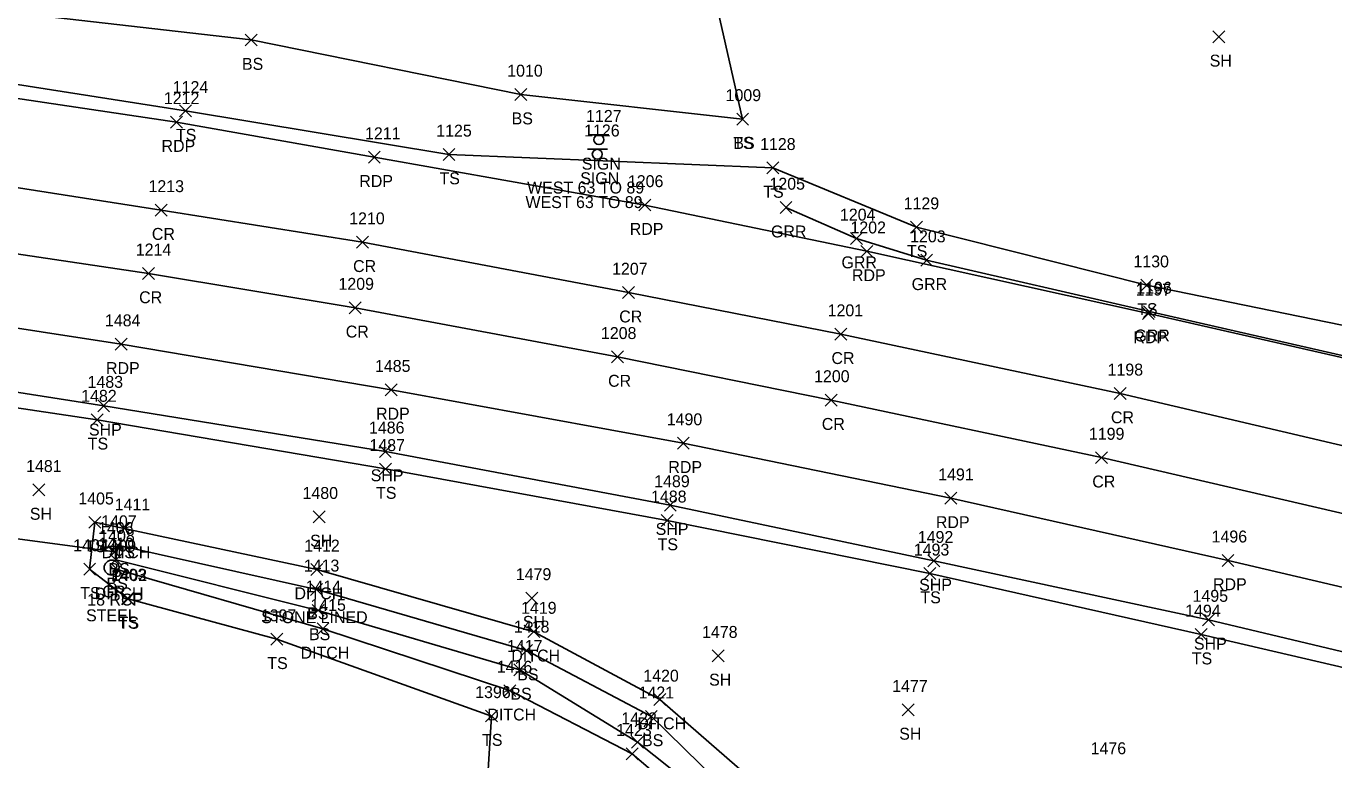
# Model space of a CAD drawing. Extents: x 1629176 to 1637209, y 606063 to 610167.
# Drawn here: x 1629563.1 to 1629782.2, y 606950 to 607073 of the extents above; entities that cross this region are included whole.
import ezdxf

# ---------------------------------------------------------------- set-up
doc = ezdxf.new("R2010")
doc.units = 0
for name, color, linetype in [('D_A', 7, 'Continuous'), ('D_C', 7, 'Continuous'), ('D_I', 7, 'Continuous'), ('D_TIC', 7, 'Continuous'), ('DCP', 7, 'Continuous'), ('DD', 7, 'Continuous'), ('L_A', 7, 'Continuous'), ('L_I', 7, 'Continuous'), ('L_TIC', 7, 'Continuous'), ('LELB', 7, 'Continuous'), ('P_A', 7, 'Continuous'), ('P_I', 7, 'Continuous'), ('P_TIC', 7, 'Continuous'), ('PET', 7, 'Continuous'), ('PRC', 7, 'Continuous'), ('PSP', 7, 'Continuous'), ('R_A', 7, 'Continuous'), ('R_C', 7, 'Continuous'), ('R_I', 7, 'Continuous'), ('R_TIC', 7, 'Continuous'), ('RGP', 7, 'Continuous'), ('RGR', 7, 'Continuous'), ('S_A', 7, 'Continuous'), ('S_C', 7, 'Continuous'), ('S_I', 7, 'Continuous'), ('SSGN', 7, 'Continuous')]:
    doc.layers.add(name, color=color, linetype=linetype)

msp = doc.modelspace()

# ---------------------------------------------------------------- linework, layer by layer
at = {"layer": 'D_TIC'}
for points in [[(1629578.49, 606987.83), (1629580.49, 606989.83)], [(1629580.49, 606987.83), (1629578.49, 606989.83)], [(1629576.96, 606983.89), (1629578.96, 606985.89)], [(1629578.96, 606983.89), (1629576.96, 606985.89)], [(1629577.34, 606980.92), (1629579.34, 606982.92)], [(1629579.34, 606980.92), (1629577.34, 606982.92)], [(1629610.81, 606980.94), (1629612.81, 606982.94)], [(1629612.81, 606980.94), (1629610.81, 606982.94)], [(1629611.83, 606971), (1629613.83, 606973)], [(1629613.83, 606971), (1629611.83, 606973)], [(1629647.15, 606970.51), (1629649.15, 606972.51)], [(1629649.15, 606970.51), (1629647.15, 606972.51)], [(1629643.13, 606960.63), (1629645.13, 606962.63)], [(1629645.13, 606960.63), (1629643.13, 606962.63)], [(1629668.27, 606959.14), (1629670.27, 606961.14)], [(1629670.27, 606959.14), (1629668.27, 606961.14)], [(1629663.65, 606950.05), (1629665.65, 606952.05)], [(1629665.65, 606950.05), (1629663.65, 606952.05)]]:
    msp.add_lwpolyline(points, dxfattribs=at)
at = {"layer": 'DCP'}
msp.add_lwpolyline([(1629240.18, 607029.98), (1629577.96, 606984.89)], dxfattribs=at)
at = {"layer": 'DD'}
for points in [[(1629579.49, 606988.83), (1629611.81, 606981.94), (1629648.15, 606971.51), (1629669.27, 606960.14), (1629688.69, 606943.21), (1629706.7, 606917.47), (1629717.05, 606898.33), (1629732.21, 606867.29)], [(1629578.34, 606981.92), (1629612.83, 606972), (1629644.13, 606961.63), (1629664.65, 606951.05), (1629679.43, 606938.38), (1629699.06, 606909.9), (1629708.92, 606897.3), (1629729.58, 606859.74)]]:
    msp.add_lwpolyline(points, dxfattribs=at)
at = {"layer": 'L_TIC'}
for points in [[(1629599.81, 607069.68), (1629601.81, 607071.68)], [(1629601.81, 607069.68), (1629599.81, 607071.68)], [(1629761.92, 607070.22), (1629763.92, 607072.22)], [(1629763.92, 607070.22), (1629761.92, 607072.22)], [(1629645, 607060.54), (1629647, 607062.54)], [(1629647, 607060.54), (1629645, 607062.54)], [(1629588.78, 607057.79), (1629590.78, 607059.79)], [(1629590.78, 607057.79), (1629588.78, 607059.79)], [(1629682.15, 607056.43), (1629684.15, 607058.43)], [(1629684.15, 607056.43), (1629682.15, 607058.43)], [(1629682.15, 607056.43), (1629684.15, 607058.43)], [(1629684.15, 607056.43), (1629682.15, 607058.43)], [(1629632.94, 607050.49), (1629634.94, 607052.49)], [(1629634.94, 607050.49), (1629632.94, 607052.49)], [(1629687.19, 607048.24), (1629689.19, 607050.24)], [(1629689.19, 607048.24), (1629687.19, 607050.24)], [(1629711.27, 607038.3), (1629713.27, 607040.3)], [(1629713.27, 607038.3), (1629711.27, 607040.3)], [(1629749.85, 607028.57), (1629751.85, 607030.57)], [(1629751.85, 607028.57), (1629749.85, 607030.57)], [(1629574, 607006.04), (1629576, 607008.04)], [(1629576, 607006.04), (1629574, 607008.04)], [(1629622.31, 606997.78), (1629624.31, 606999.78)], [(1629624.31, 606997.78), (1629622.31, 606999.78)], [(1629564.21, 606994.27), (1629566.21, 606996.27)], [(1629566.21, 606994.27), (1629564.21, 606996.27)], [(1629573.6, 606988.84), (1629575.6, 606990.84)], [(1629575.6, 606988.84), (1629573.6, 606990.84)], [(1629611.18, 606989.76), (1629613.18, 606991.76)], [(1629613.18, 606989.76), (1629611.18, 606991.76)], [(1629669.49, 606989.16), (1629671.49, 606991.16)], [(1629671.49, 606989.16), (1629669.49, 606991.16)], [(1629578.49, 606987.83), (1629580.49, 606989.83)], [(1629580.49, 606987.83), (1629578.49, 606989.83)], [(1629577.44, 606985.01), (1629579.44, 606987.01)], [(1629579.44, 606985.01), (1629577.44, 606987.01)], [(1629577.44, 606985.01), (1629579.44, 606987.01)], [(1629579.44, 606985.01), (1629577.44, 606987.01)], [(1629577.11, 606982.58), (1629579.11, 606984.58)], [(1629579.11, 606982.58), (1629577.11, 606984.58)], [(1629572.73, 606981), (1629574.73, 606983)], [(1629574.73, 606981), (1629572.73, 606983)], [(1629713.53, 606980.27), (1629715.53, 606982.27)], [(1629715.53, 606980.27), (1629713.53, 606982.27)], [(1629579.06, 606976.06), (1629581.06, 606978.06)], [(1629581.06, 606976.06), (1629579.06, 606978.06)], [(1629579.18, 606976), (1629581.18, 606978)], [(1629581.18, 606976), (1629579.18, 606978)], [(1629610.74, 606977.59), (1629612.74, 606979.59)], [(1629612.74, 606977.59), (1629610.74, 606979.59)], [(1629646.84, 606976.15), (1629648.84, 606978.15)], [(1629648.84, 606976.15), (1629646.84, 606978.15)], [(1629611.04, 606974.09), (1629613.04, 606976.09)], [(1629613.04, 606974.09), (1629611.04, 606976.09)], [(1629604.09, 606969.25), (1629606.09, 606971.25)], [(1629606.09, 606969.25), (1629604.09, 606971.25)], [(1629759, 606970.03), (1629761, 606972.03)], [(1629761, 606970.03), (1629759, 606972.03)], [(1629645.94, 606967.36), (1629647.94, 606969.36)], [(1629647.94, 606967.36), (1629645.94, 606969.36)], [(1629678.04, 606966.47), (1629680.04, 606968.47)], [(1629680.04, 606966.47), (1629678.04, 606968.47)], [(1629644.79, 606964.11), (1629646.79, 606966.11)], [(1629646.79, 606964.11), (1629644.79, 606966.11)], [(1629640.08, 606956.38), (1629642.08, 606958.38)], [(1629642.08, 606956.38), (1629640.08, 606958.38)], [(1629666.85, 606956.32), (1629668.85, 606958.32)], [(1629668.85, 606956.32), (1629666.85, 606958.32)], [(1629709.9, 606957.41), (1629711.9, 606959.41)], [(1629711.9, 606957.41), (1629709.9, 606959.41)], [(1629664.51, 606951.99), (1629666.51, 606953.99)], [(1629666.51, 606951.99), (1629664.51, 606953.99)]]:
    msp.add_lwpolyline(points, dxfattribs=at)
at = {"layer": 'LELB'}
for points in [[(1629543.77, 607066.01), (1629589.78, 607058.79), (1629633.94, 607051.49), (1629688.19, 607049.24), (1629712.27, 607039.3), (1629750.85, 607029.57), (1629792.88, 607021.01), (1629837.09, 607010.22), (1629873.61, 607000.62), (1629908.98, 606990.85), (1629926.95, 606990.99), (1629935.68, 606994), (1629949.32, 607001.7), (1629958.17, 607016.23), (1629963.63, 607035.3), (1629969.56, 607066.72), (1629971.34, 607098.85), (1629970.91, 607134.21), (1629967.52, 607170.11), (1629961.69, 607208.82), (1629957.6, 607251.36), (1629951.48, 607294.54)], [(1629676.65, 607165.93), (1629675.81, 607136.96), (1629675.04, 607107.51), (1629678.35, 607078.44), (1629683.15, 607057.43)], [(1629683.15, 607057.43), (1629646, 607061.54), (1629600.81, 607070.68), (1629551.82, 607076.32), (1629509.64, 607081.4), (1629471.16, 607085.48), (1629425.18, 607090.24), (1629387.34, 607093.37), (1629341.71, 607096.43), (1629295.02, 607099.94), (1629251.22, 607103.28), (1629239.88, 607103.86), (1629208.74, 607106), (1629183.2, 607107.98)], [(1629537.12, 607012.67), (1629575, 607007.04), (1629623.31, 606998.78), (1629670.49, 606990.16), (1629714.53, 606981.27), (1629760, 606971.03), (1629801.55, 606961.38), (1629838.05, 606950.95), (1629877.99, 606935.18), (1629884.4, 606927.34), (1629887.99, 606913), (1629884.23, 606901.72), (1629876.6, 606890.52), (1629858.53, 606872.94), (1629837.71, 606857.41), (1629816.19, 606845.34), (1629787.36, 606830.32), (1629768.49, 606822.14), (1629743.52, 606814.41), (1629718.72, 606809.85), (1629691.15, 606805.56), (1629666.46, 606804.24), (1629631.78, 606804.97), (1629589.26, 606807.01)], [(1629651.99, 606865.79), (1629638.8, 606904.11), (1629639.52, 606932.15), (1629641.08, 606957.38), (1629605.09, 606970.25), (1629580.18, 606977), (1629580.06, 606977.06), (1629573.73, 606982), (1629574.6, 606989.84), (1629579.49, 606988.83)], [(1629578.44, 606986.01), (1629578.11, 606983.58), (1629612.04, 606975.09), (1629645.79, 606965.11), (1629665.51, 606952.99), (1629682.24, 606939.68), (1629702.3, 606912.43), (1629711.51, 606897.48), (1629727.76, 606864.63)], [(1629578.44, 606986.01), (1629611.74, 606978.59), (1629646.94, 606968.36), (1629667.85, 606957.32), (1629684.26, 606941.24), (1629704.81, 606915.38), (1629714.93, 606897.63), (1629731.19, 606866.97), (1629733.06, 606863.46), (1629732.04, 606862.32), (1629730.79, 606860.62), (1629727.76, 606864.63)]]:
    msp.add_lwpolyline(points, dxfattribs=at)
at = {"layer": 'P_TIC'}
for points in [[(1629587.28, 607055.93), (1629589.28, 607057.93)], [(1629589.28, 607055.93), (1629587.28, 607057.93)], [(1629620.43, 607050.04), (1629622.43, 607052.04)], [(1629622.43, 607050.04), (1629620.43, 607052.04)], [(1629584.72, 607041.18), (1629586.72, 607043.18)], [(1629586.72, 607041.18), (1629584.72, 607043.18)], [(1629665.74, 607042.02), (1629667.74, 607044.02)], [(1629667.74, 607042.02), (1629665.74, 607044.02)], [(1629618.43, 607035.79), (1629620.43, 607037.79)], [(1629620.43, 607035.79), (1629618.43, 607037.79)], [(1629702.98, 607034.26), (1629704.98, 607036.26)], [(1629704.98, 607034.26), (1629702.98, 607036.26)], [(1629582.59, 607030.56), (1629584.59, 607032.56)], [(1629584.59, 607030.56), (1629582.59, 607032.56)], [(1629663.04, 607027.34), (1629665.04, 607029.34)], [(1629665.04, 607027.34), (1629663.04, 607029.34)], [(1629617.2, 607024.81), (1629619.2, 607026.81)], [(1629619.2, 607024.81), (1629617.2, 607026.81)], [(1629750.13, 607023.85), (1629752.13, 607025.85)], [(1629752.13, 607023.85), (1629750.13, 607025.85)], [(1629698.59, 607020.37), (1629700.59, 607022.37)], [(1629700.59, 607020.37), (1629698.59, 607022.37)], [(1629577.99, 607018.69), (1629579.99, 607020.69)], [(1629579.99, 607018.69), (1629577.99, 607020.69)], [(1629661.17, 607016.56), (1629663.17, 607018.56)], [(1629663.17, 607016.56), (1629661.17, 607018.56)], [(1629623.23, 607011.05), (1629625.23, 607013.05)], [(1629625.23, 607011.05), (1629623.23, 607013.05)], [(1629575.08, 607008.38), (1629577.08, 607010.38)], [(1629577.08, 607008.38), (1629575.08, 607010.38)], [(1629696.98, 607009.33), (1629698.98, 607011.33)], [(1629698.98, 607009.33), (1629696.98, 607011.33)], [(1629745.42, 607010.44), (1629747.42, 607012.44)], [(1629747.42, 607010.44), (1629745.42, 607012.44)], [(1629672.21, 607002.11), (1629674.21, 607004.11)], [(1629674.21, 607002.11), (1629672.21, 607004.11)], [(1629622.28, 607000.72), (1629624.28, 607002.72)], [(1629624.28, 607000.72), (1629622.28, 607002.72)], [(1629742.3, 606999.68), (1629744.3, 607001.68)], [(1629744.3, 606999.68), (1629742.3, 607001.68)], [(1629670.03, 606991.73), (1629672.03, 606993.73)], [(1629672.03, 606991.73), (1629670.03, 606993.73)], [(1629717.04, 606992.87), (1629719.04, 606994.87)], [(1629719.04, 606992.87), (1629717.04, 606994.87)], [(1629714.19, 606982.38), (1629716.19, 606984.38)], [(1629716.19, 606982.38), (1629714.19, 606984.38)], [(1629763.48, 606982.46), (1629765.48, 606984.46)], [(1629765.48, 606982.46), (1629763.48, 606984.46)], [(1629760.23, 606972.52), (1629762.23, 606974.52)], [(1629762.23, 606972.52), (1629760.23, 606974.52)]]:
    msp.add_lwpolyline(points, dxfattribs=at)
at = {"layer": 'PET'}
for points in [[(1630115.59, 606918.47), (1630070.26, 606934.37), (1630047.19, 606942.61), (1630027.81, 606949.5), (1629999.64, 606958.79), (1629963.88, 606969.73), (1629916.37, 606983.66), (1629883.8, 606991.87), (1629841.7, 607003.38), (1629794.53, 607014.94), (1629751.13, 607024.85), (1629703.98, 607035.26), (1629666.74, 607043.02), (1629621.43, 607051.04), (1629588.28, 607056.93), (1629542.89, 607063.67), (1629493.94, 607070.34), (1629447.94, 607075.86), (1629406.53, 607080.22), (1629360.37, 607084.28), (1629316.73, 607087.48), (1629269.81, 607090.12), (1629227.29, 607092.24), (1629182.92, 607093.47)], [(1629181.97, 607055.08), (1629220.58, 607054.17), (1629264.89, 607052.3), (1629300.55, 607050.62), (1629344.63, 607047.49), (1629382.7, 607044.36), (1629427.5, 607039.91), (1629466.96, 607035.43), (1629507.21, 607030.19), (1629538.75, 607025.9), (1629578.99, 607019.69), (1629624.23, 607012.05), (1629673.21, 607003.11), (1629718.04, 606993.87), (1629764.48, 606983.46), (1629805.04, 606973.93), (1629842.82, 606964.4), (1629884.8, 606953.15), (1629930.25, 606940.34), (1629964.97, 606930.13), (1630005.89, 606916.45), (1630050.76, 606901.68), (1630096.23, 606885.67)]]:
    msp.add_lwpolyline(points, dxfattribs=at)
at = {"layer": 'PRC'}
for points in [[(1630110.18, 606905.77), (1630065.36, 606921.68), (1630022.36, 606935.68), (1629994.71, 606945.36), (1629959.54, 606955.86), (1629913.54, 606969.37), (1629877.41, 606979.26), (1629837.69, 606989.99), (1629791.63, 607000.82), (1629746.42, 607011.44), (1629699.59, 607021.37), (1629664.04, 607028.34), (1629619.43, 607036.79), (1629585.72, 607042.18), (1629539.96, 607049.3), (1629491.45, 607056.02), (1629445.88, 607061.28), (1629404.36, 607066.23), (1629358.89, 607069.49), (1629314.63, 607073.29), (1629269.37, 607075.36), (1629226.58, 607077.32), (1629182.35, 607078.58)], [(1630105.99, 606894.95), (1630061.18, 606910.94), (1630017.61, 606925.74), (1629991.01, 606934.32), (1629955.3, 606944.84), (1629910.77, 606959.12), (1629874.52, 606969.06), (1629834.93, 606979.4), (1629788.74, 606990.13), (1629743.3, 607000.68), (1629697.98, 607010.33), (1629662.17, 607017.56), (1629618.2, 607025.81), (1629583.59, 607031.56), (1629540.4, 607037.95), (1629489.63, 607045.02), (1629444.26, 607050.14), (1629402.79, 607054.66), (1629359.1, 607058.26), (1629313.06, 607061.88), (1629268.47, 607063.97), (1629226.23, 607065.89), (1629182.22, 607066.96)]]:
    msp.add_lwpolyline(points, dxfattribs=at)
at = {"layer": 'PSP'}
msp.add_lwpolyline([(1629181.26, 607044.82), (1629219.33, 607043.61), (1629263.7, 607041.6), (1629300.14, 607039.68), (1629342.49, 607036.76), (1629381.41, 607033.8), (1629425.61, 607029.43), (1629465.11, 607025.03), (1629505.36, 607019.79), (1629537.56, 607015.39), (1629576.08, 607009.38), (1629623.28, 607001.72), (1629671.03, 606992.73), (1629715.19, 606983.38), (1629761.23, 606973.52), (1629802.25, 606963.72), (1629839.3, 606954.1), (1629871.33, 606945.94), (1629930.37, 606928.51), (1629965.2, 606918.43), (1630003.07, 606906.25), (1630045.28, 606892.75), (1630092.08, 606875.64)], dxfattribs=at)
at = {"layer": 'R_TIC'}
for points in [[(1629689.41, 607041.59), (1629691.41, 607043.59)], [(1629691.41, 607041.59), (1629689.41, 607043.59)], [(1629701.23, 607036.41), (1629703.23, 607038.41)], [(1629703.23, 607036.41), (1629701.23, 607038.41)], [(1629712.98, 607032.77), (1629714.98, 607034.77)], [(1629714.98, 607032.77), (1629712.98, 607034.77)], [(1629750.3, 607024.15), (1629752.3, 607026.15)], [(1629752.3, 607024.15), (1629750.3, 607026.15)]]:
    msp.add_lwpolyline(points, dxfattribs=at)
at = {"layer": 'RGP'}
msp.add_line((1629577.41, 606982.25), (1629577.41, 606982.25), dxfattribs=at)
for radius in [1.25, 0.0833]:
    msp.add_circle((1629577.41, 606982.25), radius, dxfattribs=at)
at = {"layer": 'RGR'}
msp.add_lwpolyline([(1629943.69, 607384.05), (1629950.32, 607332.08), (1629955.32, 607294.81), (1629961.02, 607247.36), (1629965.35, 607210.17), (1629970.15, 607169.34), (1629972.95, 607135.74), (1629974.05, 607104.82), (1629973.08, 607080.23), (1629970.56, 607055.99), (1629966.4, 607033.17), (1629961.24, 607015.58), (1629955.46, 607004.39), (1629949.06, 606997.06), (1629936.39, 606990.57), (1629926.1, 606987.63), (1629916.88, 606985.75), (1629884.2, 606992.74), (1629842, 607003.78), (1629794.61, 607015.29), (1629751.3, 607025.15), (1629713.98, 607033.77), (1629702.23, 607037.41), (1629690.41, 607042.59)], dxfattribs=at)
at = {"layer": 'SSGN'}
for p, q in [((1629657.41, 607054.8), (1629660.75, 607054.8)), ((1629657.14, 607052.37), (1629660.48, 607052.37)), ((1629659.06, 607053.97), (1629659.06, 607053.97)), ((1629658.79, 607051.53), (1629658.79, 607051.53))]:
    msp.add_line(p, q, dxfattribs=at)
for centre in [(1629659.06, 607053.97), (1629658.79, 607051.53)]:
    msp.add_circle(centre, 0.833, dxfattribs=at)

# ---------------------------------------------------------------- texts
at = {"layer": 'D_A'}
for s, p in [('DITCH', (1629575.73, 606983.83)), ('P', (1629577.34, 606979.89)), ('DITCH', (1629574.58, 606976.92)), ('DITCH', (1629608.05, 606976.94)), ('DITCH', (1629609.07, 606967)), ('DITCH', (1629644.39, 606966.51)), ('DITCH', (1629640.37, 606956.63)), ('DITCH', (1629665.51, 606955.14))]:
    msp.add_text(s, height=2, dxfattribs=at).set_placement(p)
at = {"layer": 'D_C'}
for s, p in [('18 RCP', (1629573.33, 606975.89)), ('STONE LINED', (1629602.48, 606972.94))]:
    msp.add_text(s, height=2, dxfattribs=at).set_placement(p)
at = {"layer": 'D_I'}
for s, p in [('1411', (1629577.93, 606991.83)), ('1406', (1629575.14, 606987.89)), ('1409', (1629575.56, 606984.92)), ('1412', (1629609.69, 606984.94)), ('1415', (1629610.71, 606975)), ('1419', (1629646.02, 606974.51)), ('1416', (1629641.95, 606964.63)), ('1420', (1629666.5, 606963.14)), ('1423', (1629661.96, 606954.05))]:
    msp.add_text(s, height=2, dxfattribs=at).set_placement(p)
at = {"layer": 'L_A'}
for s, p in [('BS', (1629599.25, 607065.68)), ('SH', (1629761.41, 607066.22)), ('BS', (1629644.44, 607056.54)), ('TS', (1629588.19, 607053.79)), ('TS', (1629681.56, 607052.43)), ('BS', (1629681.59, 607052.43)), ('TS', (1629632.35, 607046.49)), ('TS', (1629686.6, 607044.24)), ('TS', (1629710.68, 607034.3)), ('TS', (1629749.26, 607024.57)), ('TS', (1629573.41, 607002.04)), ('TS', (1629621.72, 606993.78)), ('SH', (1629563.7, 606990.27)), ('TS', (1629573.01, 606984.84)), ('SH', (1629610.67, 606985.76)), ('TS', (1629668.9, 606985.16)), ('TS', (1629577.9, 606983.83)), ('BS', (1629576.88, 606981.01)), ('BS', (1629576.88, 606981.01)), ('BS', (1629576.55, 606978.58)), ('TS', (1629572.14, 606977)), ('TS', (1629712.94, 606976.27)), ('BS', (1629610.18, 606973.59)), ('TS', (1629578.47, 606972.06)), ('TS', (1629578.59, 606972)), ('SH', (1629646.32, 606972.15)), ('BS', (1629610.48, 606970.09)), ('TS', (1629603.5, 606965.25)), ('TS', (1629758.41, 606966.03)), ('BS', (1629645.38, 606963.36)), ('SH', (1629677.53, 606962.47)), ('BS', (1629644.23, 606960.11)), ('TS', (1629639.49, 606952.38)), ('BS', (1629666.29, 606952.32)), ('SH', (1629709.39, 606953.41))]:
    msp.add_text(s, height=2, dxfattribs=at).set_placement(p)
at = {"layer": 'L_I'}
for s, p in [('1010', (1629643.7, 607064.54)), ('1124', (1629587.65, 607061.79)), ('1009', (1629680.29, 607060.43)), ('1009', (1629680.29, 607060.43)), ('1125', (1629631.81, 607054.49)), ('1128', (1629686.07, 607052.24)), ('1129', (1629710.13, 607042.3)), ('1130', (1629748.63, 607032.57)), ('1482', (1629572.31, 607010.04)), ('1487', (1629620.61, 607001.78)), ('1481', (1629563.08, 606998.27)), ('1480', (1629609.4, 606993.76)), ('1488', (1629667.8, 606993.16)), ('1405', (1629571.83, 606992.84)), ('1411', (1629577.93, 606991.83)), ('1407', (1629575.66, 606989.01)), ('1407', (1629575.66, 606989.01)), ('1408', (1629575.34, 606986.58)), ('1404', (1629570.96, 606985)), ('1493', (1629711.83, 606984.27)), ('1403', (1629577.29, 606980.06)), ('1402', (1629577.41, 606980)), ('1413', (1629609.62, 606981.59)), ('1479', (1629645.14, 606980.15)), ('1414', (1629609.92, 606978.09)), ('1397', (1629602.4, 606973.25)), ('1494', (1629757.3, 606974.03)), ('1418', (1629644.82, 606971.36)), ('1478', (1629676.35, 606970.47)), ('1417', (1629643.67, 606968.11)), ('1396', (1629638.33, 606960.38)), ('1421', (1629665.72, 606960.32)), ('1477', (1629708.21, 606961.41)), ('1422', (1629662.82, 606955.99)), ('1476', (1629741.46, 606950.97))]:
    msp.add_text(s, height=2, dxfattribs=at).set_placement(p)
at = {"layer": 'P_A'}
for s, p in [('RDP', (1629585.77, 607051.93)), ('RDP', (1629618.91, 607046.04)), ('CR', (1629584.15, 607037.18)), ('RDP', (1629664.23, 607038.02)), ('CR', (1629617.87, 607031.79)), ('RDP', (1629701.47, 607030.26)), ('CR', (1629582.02, 607026.56)), ('CR', (1629662.47, 607023.34)), ('CR', (1629616.64, 607020.81)), ('RDP', (1629748.62, 607019.85)), ('CR', (1629698.03, 607016.37)), ('RDP', (1629576.47, 607014.69)), ('CR', (1629660.6, 607012.56)), ('RDP', (1629621.72, 607007.05)), ('CR', (1629744.86, 607006.44)), ('SHP', (1629573.61, 607004.38)), ('CR', (1629696.41, 607005.33)), ('RDP', (1629670.7, 606998.11)), ('SHP', (1629620.82, 606996.72)), ('CR', (1629741.74, 606995.68)), ('RDP', (1629715.53, 606988.87)), ('SHP', (1629668.57, 606987.73)), ('SHP', (1629712.73, 606978.38)), ('RDP', (1629761.97, 606978.46)), ('SHP', (1629758.77, 606968.52))]:
    msp.add_text(s, height=2, dxfattribs=at).set_placement(p)
at = {"layer": 'P_I'}
for s, p in [('1212', (1629586.16, 607059.93)), ('1211', (1629619.87, 607054.04)), ('1206', (1629663.92, 607046.02)), ('1213', (1629583.59, 607045.18)), ('1210', (1629617.22, 607039.79)), ('1202', (1629701.21, 607038.26)), ('1214', (1629581.46, 607034.56)), ('1207', (1629661.27, 607031.34)), ('1209', (1629615.42, 607028.81)), ('1197', (1629749, 607027.85)), ('1201', (1629697.39, 607024.37)), ('1484', (1629576.29, 607022.69)), ('1208', (1629659.4, 607020.56)), ('1485', (1629621.54, 607015.05)), ('1200', (1629695.12, 607013.33)), ('1198', (1629744.3, 607014.44)), ('1483', (1629573.38, 607012.38)), ('1490', (1629670.43, 607006.11)), ('1486', (1629620.53, 607004.72)), ('1199', (1629741.17, 607003.68)), ('1489', (1629668.33, 606995.73)), ('1491', (1629715.92, 606996.87)), ('1492', (1629712.5, 606986.38)), ('1496', (1629761.73, 606986.46)), ('1495', (1629758.54, 606976.52))]:
    msp.add_text(s, height=2, dxfattribs=at).set_placement(p)
at = {"layer": 'R_A'}
for s, p in [('GRR', (1629687.9, 607037.59)), ('GRR', (1629699.71, 607032.41)), ('GRR', (1629711.47, 607028.77)), ('GRR', (1629748.79, 607020.15)), ('GP', (1629575.84, 606977.25))]:
    msp.add_text(s, height=2, dxfattribs=at).set_placement(p)
at = {"layer": 'R_C'}
msp.add_text('STEEL', height=2, dxfattribs=at).set_placement((1629573.13, 606973.25))
at = {"layer": 'R_I'}
for s, p in [('1205', (1629687.64, 607045.59)), ('1204', (1629699.45, 607040.41)), ('1203', (1629711.21, 607036.77)), ('1196', (1629749.12, 607028.15)), ('1410', (1629575.2, 606985.25))]:
    msp.add_text(s, height=2, dxfattribs=at).set_placement(p)
at = {"layer": 'S_A'}
for p in [(1629656.2, 607048.95), (1629655.93, 607046.51)]:
    msp.add_text('SIGN', height=2, dxfattribs=at).set_placement(p)
at = {"layer": 'S_C'}
for p in [(1629647.03, 607044.95), (1629646.76, 607042.51)]:
    msp.add_text('WEST 63 TO 89', height=2, dxfattribs=at).set_placement(p)
at = {"layer": 'S_I'}
for s, p in [('1127', (1629656.91, 607056.95)), ('1126', (1629656.59, 607054.51))]:
    msp.add_text(s, height=2, dxfattribs=at).set_placement(p)

doc.saveas('drawing.dxf')
